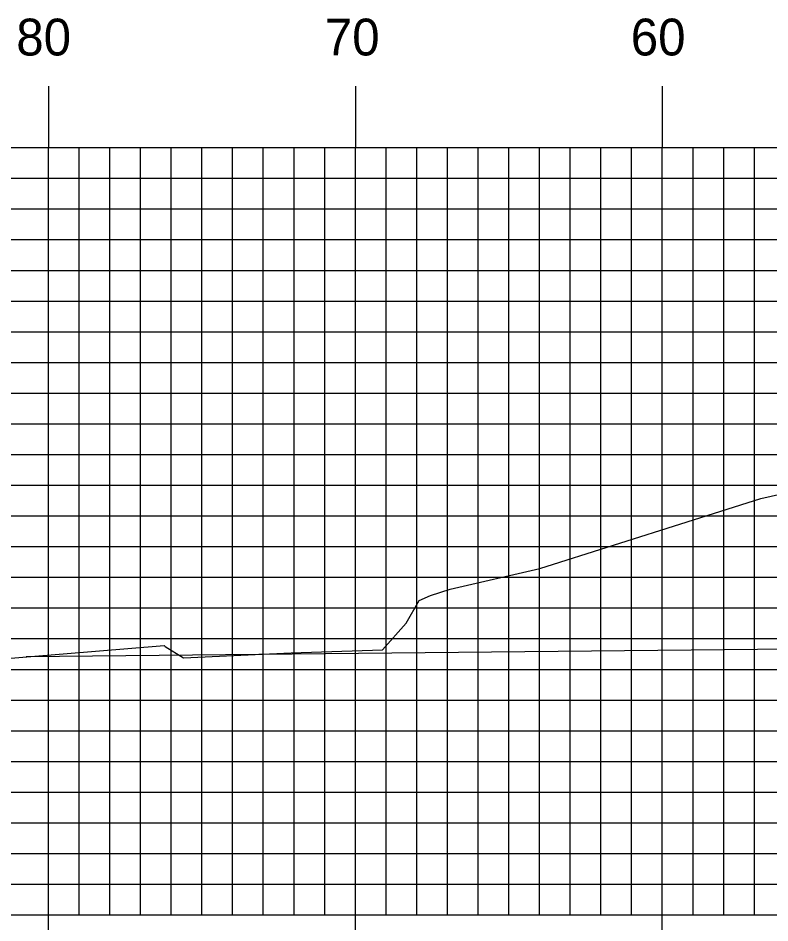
# Model space of a CAD drawing. Extents: x 1823571 to 1823914, y 442310 to 442530.
# Drawn here: x 1823655.91 to 1823680.41, y 442327.85 to 442357.33 of the extents above; entities that cross this region are included whole.
import ezdxf

# ---------------------------------------------------------------- set-up
doc = ezdxf.new("R2010")
doc.units = 0
for name, color, linetype in [('D_Roadway_SlopeLines', 7, 'Continuous'), ('H_V ANNOTATION', 7, 'Continuous'), ('MAJOR', 7, 'Continuous'), ('MINOR', 7, 'Continuous'), ('S_Roadway_Centerline', 7, 'Continuous')]:
    doc.layers.add(name, color=color, linetype=linetype)

msp = doc.modelspace()

# ---------------------------------------------------------------- linework, layer by layer
at = {"layer": 'D_Roadway_SlopeLines'}
msp.add_line((1823682.147, 442336.784), (1823656.168, 442336.524), dxfattribs=at)
at = {"layer": 'MAJOR'}
for p, q in [((1823656.9, 442355.119), (1823656.9, 442353.115)), ((1823666.9, 442355.119), (1823666.9, 442353.115)), ((1823676.9, 442355.119), (1823676.9, 442353.115)), ((1823596.9, 442353.115), (1823876.9, 442353.115)), ((1823656.9, 442328.115), (1823656.9, 442353.115)), ((1823666.9, 442328.115), (1823666.9, 442353.115)), ((1823676.9, 442328.115), (1823676.9, 442353.115)), ((1823596.9, 442348.115), (1823876.9, 442348.115)), ((1823596.9, 442343.115), (1823876.9, 442343.115)), ((1823596.9, 442338.115), (1823876.9, 442338.115)), ((1823596.9, 442333.115), (1823876.9, 442333.115)), ((1823596.9, 442328.115), (1823876.9, 442328.115)), ((1823596.9, 442328.115), (1823876.9, 442328.115)), ((1823656.9, 442326.111), (1823656.9, 442328.115)), ((1823666.9, 442326.111), (1823666.9, 442328.115)), ((1823676.9, 442326.111), (1823676.9, 442328.115))]:
    msp.add_line(p, q, dxfattribs=at)
at = {"layer": 'MINOR'}
for p, q in [((1823657.9, 442328.115), (1823657.9, 442353.115)), ((1823658.9, 442328.115), (1823658.9, 442353.115)), ((1823659.9, 442328.115), (1823659.9, 442353.115)), ((1823660.9, 442328.115), (1823660.9, 442353.115)), ((1823661.9, 442328.115), (1823661.9, 442353.115)), ((1823662.9, 442328.115), (1823662.9, 442353.115)), ((1823663.9, 442328.115), (1823663.9, 442353.115)), ((1823664.9, 442328.115), (1823664.9, 442353.115)), ((1823665.9, 442328.115), (1823665.9, 442353.115)), ((1823667.9, 442328.115), (1823667.9, 442353.115)), ((1823668.9, 442328.115), (1823668.9, 442353.115)), ((1823669.9, 442328.115), (1823669.9, 442353.115)), ((1823670.9, 442328.115), (1823670.9, 442353.115)), ((1823671.9, 442328.115), (1823671.9, 442353.115)), ((1823672.9, 442328.115), (1823672.9, 442353.115)), ((1823673.9, 442328.115), (1823673.9, 442353.115)), ((1823674.9, 442328.115), (1823674.9, 442353.115)), ((1823675.9, 442328.115), (1823675.9, 442353.115)), ((1823677.9, 442328.115), (1823677.9, 442353.115)), ((1823678.9, 442328.115), (1823678.9, 442353.115)), ((1823679.9, 442328.115), (1823679.9, 442353.115)), ((1823596.9, 442352.115), (1823876.9, 442352.115)), ((1823596.9, 442351.115), (1823876.9, 442351.115)), ((1823596.9, 442350.115), (1823876.9, 442350.115)), ((1823596.9, 442349.115), (1823876.9, 442349.115)), ((1823596.9, 442347.115), (1823876.9, 442347.115)), ((1823596.9, 442346.115), (1823876.9, 442346.115)), ((1823596.9, 442345.115), (1823876.9, 442345.115)), ((1823596.9, 442344.115), (1823876.9, 442344.115)), ((1823596.9, 442342.115), (1823876.9, 442342.115)), ((1823596.9, 442341.115), (1823876.9, 442341.115)), ((1823596.9, 442340.115), (1823876.9, 442340.115)), ((1823596.9, 442339.115), (1823876.9, 442339.115)), ((1823596.9, 442337.115), (1823876.9, 442337.115)), ((1823596.9, 442336.115), (1823876.9, 442336.115)), ((1823596.9, 442335.115), (1823876.9, 442335.115)), ((1823596.9, 442334.115), (1823876.9, 442334.115)), ((1823596.9, 442332.115), (1823876.9, 442332.115)), ((1823596.9, 442331.115), (1823876.9, 442331.115)), ((1823596.9, 442330.115), (1823876.9, 442330.115)), ((1823596.9, 442329.115), (1823876.9, 442329.115))]:
    msp.add_line(p, q, dxfattribs=at)
at = {"layer": 'S_Roadway_Centerline'}
msp.add_lwpolyline([(1823647.499, 442335.81), (1823660.666, 442336.895), (1823660.701, 442336.862), (1823661.299, 442336.486), (1823664.812, 442336.656), (1823667.78, 442336.747), (1823668.55, 442337.618), (1823668.979, 442338.358), (1823669.349, 442338.518), (1823669.986, 442338.723), (1823672.905, 442339.405), (1823680.111, 442341.679), (1823683.481, 442342.441), (1823685.979, 442343.112), (1823688.135, 442343.343), (1823688.698, 442343.404), (1823691.213, 442343.395), (1823691.687, 442343.419), (1823696.395, 442343.77), (1823702.49, 442343.867), (1823705.023, 442344.116), (1823708.497, 442344.256)], dxfattribs=at)

# ---------------------------------------------------------------- texts
at = {"layer": 'H_V ANNOTATION'}
for s, p in [('80', (1823655.851, 442356.115)), ('70', (1823665.904, 442356.115)), ('60', (1823675.872, 442356.115))]:
    msp.add_text(s, height=1.2, dxfattribs=at).set_placement(p)

doc.saveas('drawing.dxf')
